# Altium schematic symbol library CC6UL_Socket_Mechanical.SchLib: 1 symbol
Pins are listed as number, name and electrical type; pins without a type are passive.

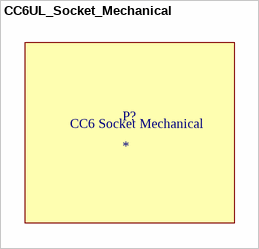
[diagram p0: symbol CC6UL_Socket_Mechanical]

## CC6UL_Socket_Mechanical
designator P?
